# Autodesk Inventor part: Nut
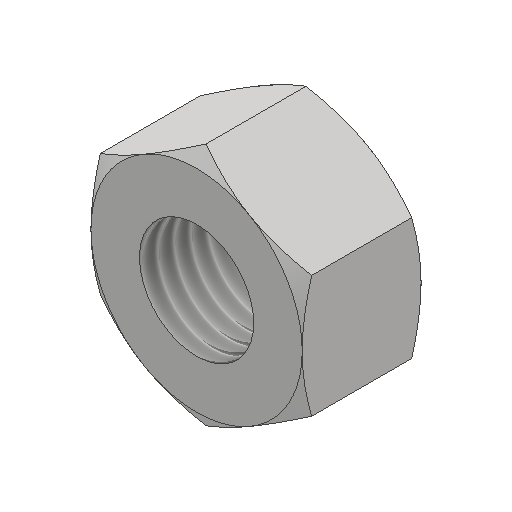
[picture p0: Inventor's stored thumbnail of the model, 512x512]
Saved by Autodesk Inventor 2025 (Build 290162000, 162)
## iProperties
Created: 2016-05
Part Number: Nut
Material: Generic
Document SubType Name: Modeling
Designer: CADCIM
Density: 1 g/cm^3
Appearance: Default
Author: CADCIM
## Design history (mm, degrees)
sketch "Sketch1"
  geometry: L1 (9.6, -5.543)-(0, -11.085); L2 (0, -11.085)-(-9.6, -5.543); L3 (-9.6, -5.543)-(-9.6, 5.543); L4 (-9.6, 5.543)-(0, 11.085); L5 (0, 11.085)-(9.6, 5.543); L6 (9.6, 5.543)-(9.6, -5.543); 2 further points
  constraints: 12 end point, 1 coincident, 1 vertical alignment, 13 other
  dimensions: "d0" = 19.2 distance between parallel lines of L3 L6
extrude "Extrusion1" new body sketch "Sketch1" distance "d1" = 10.8; taper "d2" = 0 deg
sketch "Sketch2"
  geometry: L1 (0, 11.085)-(-9.6, 5.543) reference; C1 r 9.6 at (0, 0); 1 further point
  constraints: 1 centre point, 1 coincident, 1 tangent
extrude "Extrusion2" sketch "Sketch2" distance "d3" = 10.8; taper "d4" = 60 deg
sketch "Sketch3"
  geometry: L1 (0, -11.085)-(9.6, -5.543) reference; C1 r 9.6 at (0, 0); 1 further point
  constraints: 1 centre point, 1 coincident, 1 tangent
extrude "Extrusion3" sketch "Sketch3" distance "d5" = 10.8; taper "d6" = 60 deg
workplane "Work Plane1"
hole "Hole1" diameter "d9" = 10.376; stored, may be unused: countersink angle "d13" = 90 deg, drill point angle "d15" = 118 deg; dims "d7" = 10, "d8" = 10, "d10" = 24, "d11" = 4, "d12" = 2, "d14" = 31.3
body "Solid1"
sketch "Sketch4"
  geometry: 1 further point
